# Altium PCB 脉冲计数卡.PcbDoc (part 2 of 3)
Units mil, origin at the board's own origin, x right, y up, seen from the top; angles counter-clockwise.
Board outline 5137.66 x 6771.53 mil, 4 copper layers (Top Layer, GND, VCC, Bottom Layer); 160 components, 225 nets, 1035 pads, 287 vias.
Unrouted connection lines stored in the file: 61.
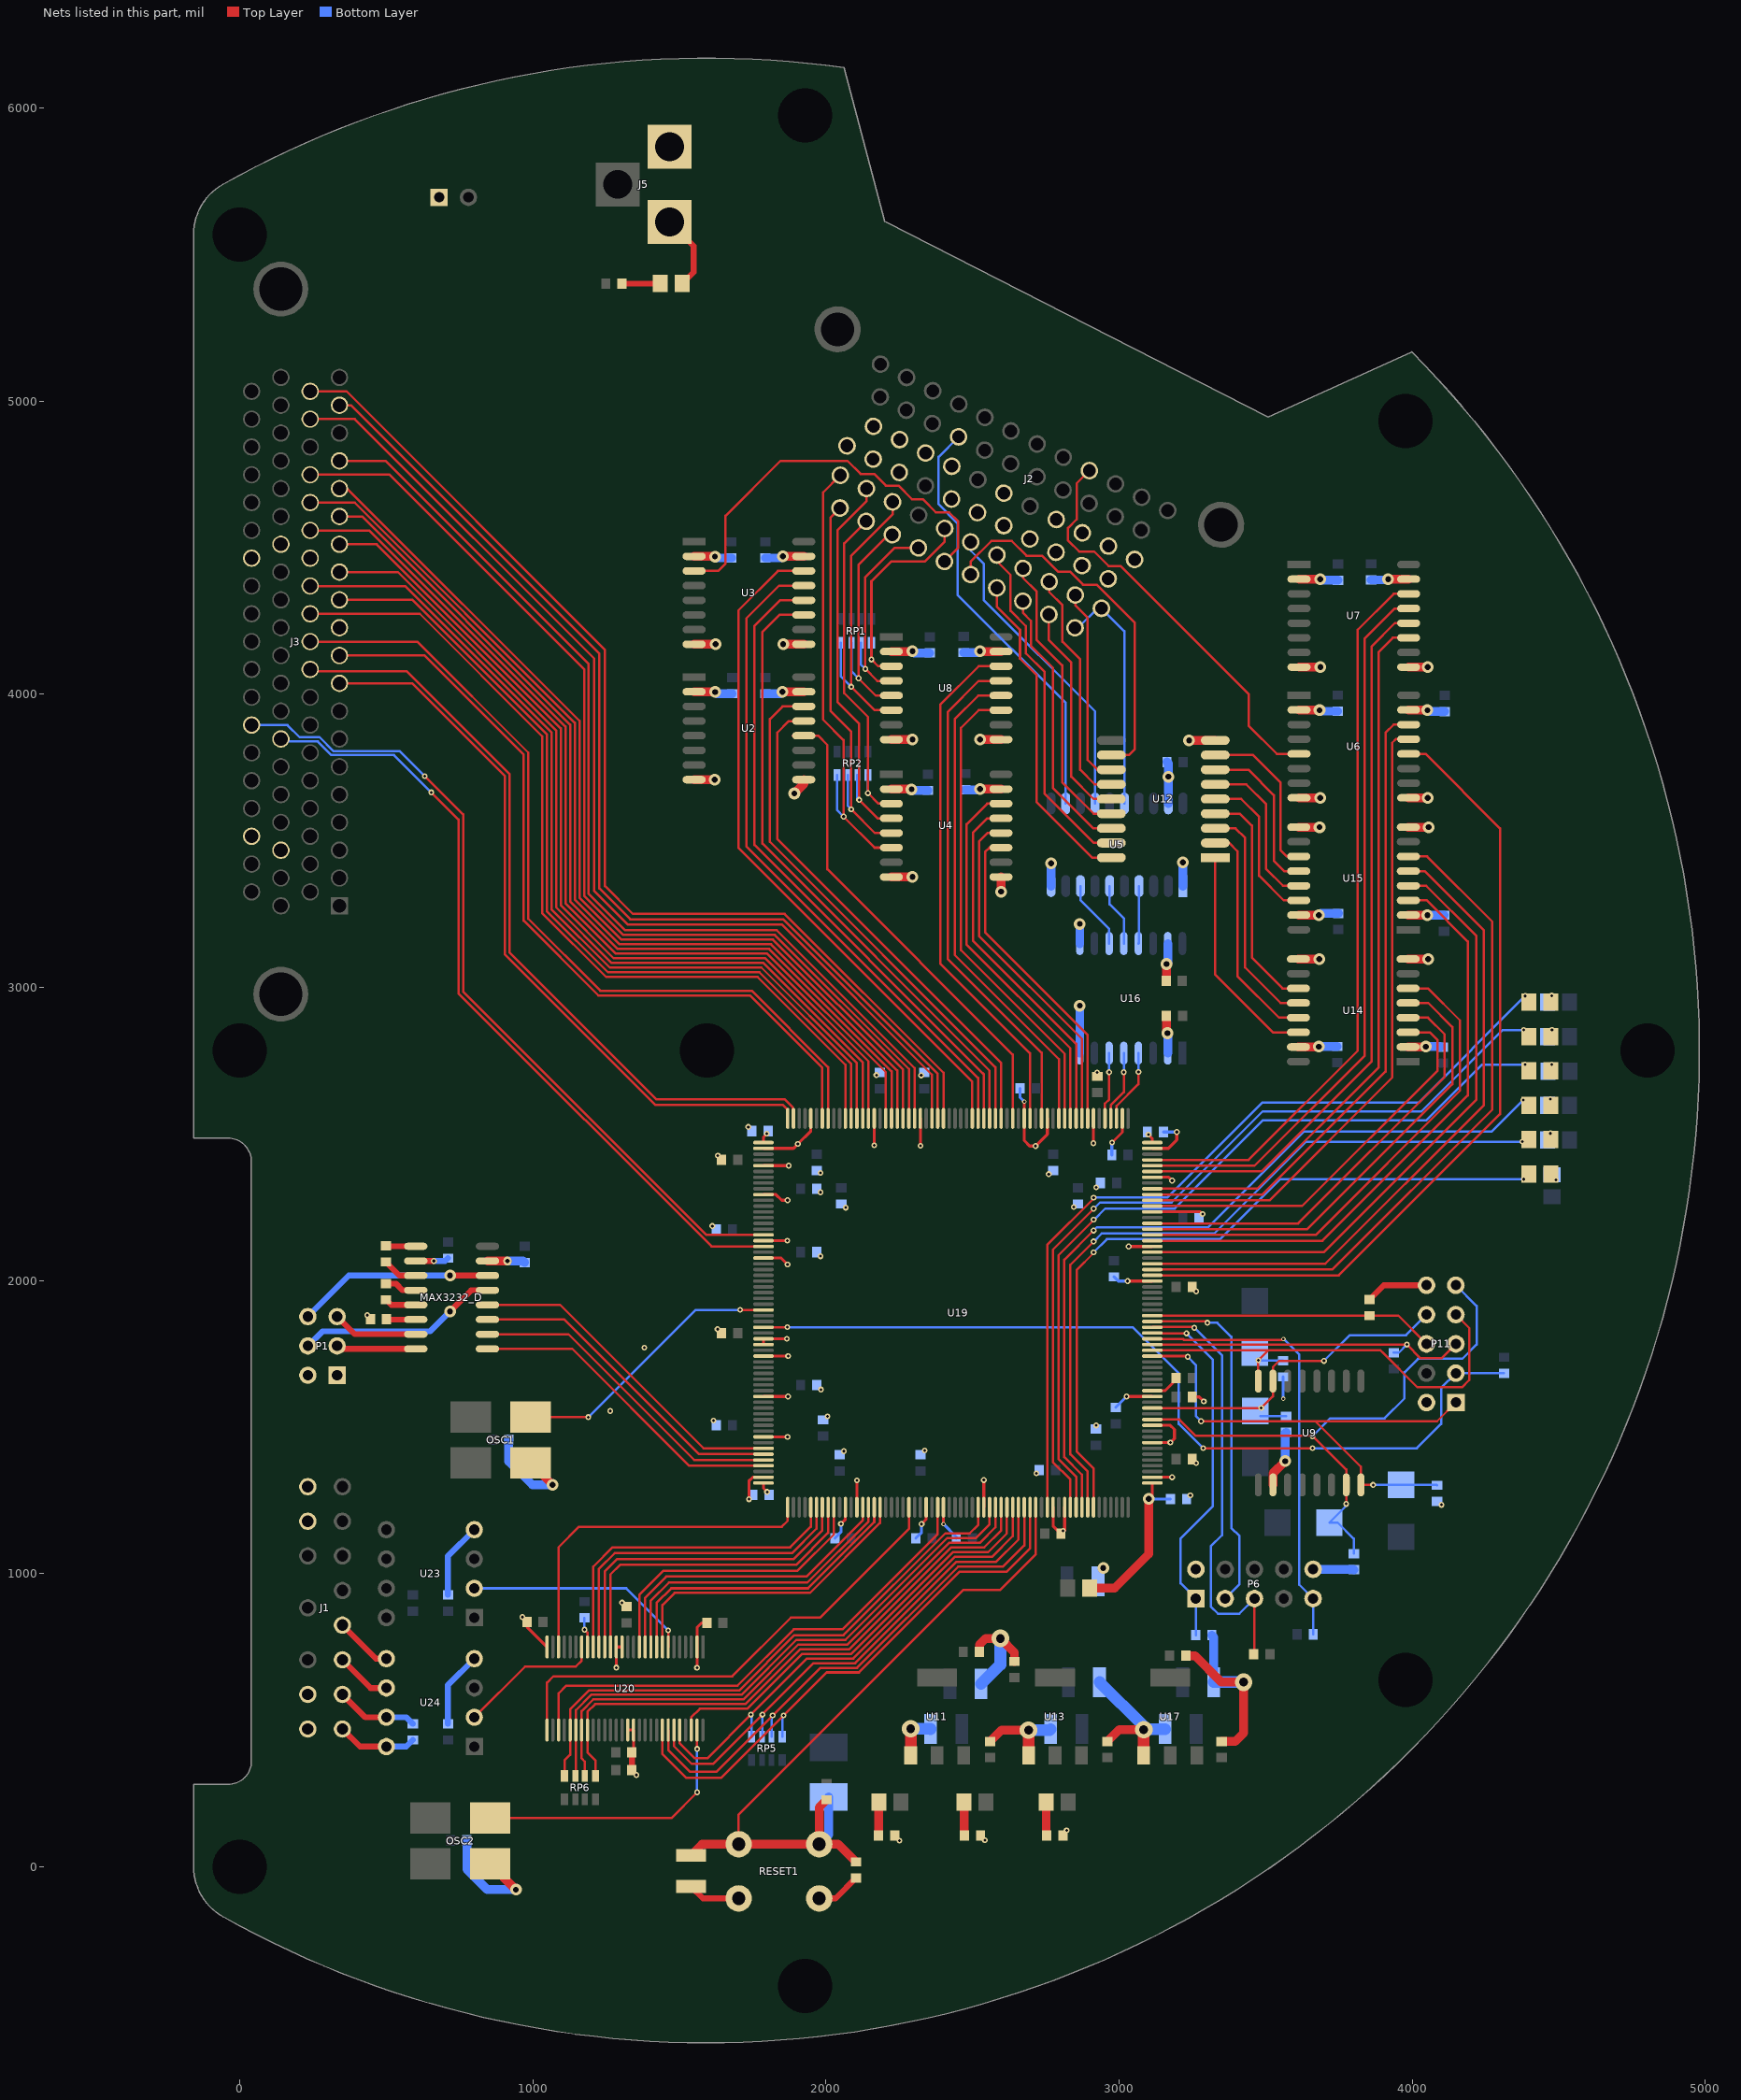
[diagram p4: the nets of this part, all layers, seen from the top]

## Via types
v1: diameter 20, hole 10, Top Layer to Bottom Layer, 184 vias
v2: diameter 40, hole 20, Top Layer to Bottom Layer, 82 vias
v3: diameter 15, hole 8, Top Layer to Bottom Layer, 11 vias
v4: diameter 60, hole 30, Top Layer to Bottom Layer, 8 vias
v5: diameter 30, hole 15, Top Layer to Bottom Layer, 2 vias

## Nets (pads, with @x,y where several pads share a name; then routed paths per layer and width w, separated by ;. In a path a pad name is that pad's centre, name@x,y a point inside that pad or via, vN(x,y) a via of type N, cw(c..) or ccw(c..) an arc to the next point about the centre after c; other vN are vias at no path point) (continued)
AA0: U12.7 U15.12 | length 559.5
  Top Layer w8: U12.7@3328,3743 3441,3743 3528,3656 3528,3432 3563,3397 U15.12@3612.98,3397
AA1: U12.5 U15.14 | length 546
  Top Layer w8: U12.5@3328,3643 3417,3643 3478,3582 3478,3381 3562,3297 U15.14@3612.98,3297
AA2: U12.6 U15.13 | length 557.8
  Top Layer w8: U12.6@3328,3693 3434,3693 3502,3625 3502,3404 3559,3347 U15.13@3612.98,3347
AA3: U12.3 U14.12 | length 789.8
  Top Layer w8: U12.3@3328,3543 3397,3543 3430,3510 3430,3068 3551,2947 U14.12@3611.98,2947
AA4: U12.4 U14.11 | length 794.5
  Top Layer w8: U12.4@3328,3593 3412,3593 3453,3552 3453,3102 3558,2997 U14.11@3611.98,2997
AA5: U12.1 U14.14 | length 764.6
  Top Layer w8: U12.1@3328,3443 3328,3044 3525,2847 U14.14@3611.98,2847
AA6: U12.2 U14.13 | length 780.4
  Top Layer w8: U12.2@3328,3493 3376,3493 3404,3465 3404,3039 3546,2897 U14.13@3611.98,2897
AA7: U12.8 U15.11 | length 563.6
  Top Layer w8: U12.8@3328,3793 3457,3793 3551,3699 3551,3468 3572,3447 U15.11@3612.98,3447
AB0: J2.48 U12.12 | length 627.2
  Top Layer w8: J2.48@2850.66,4338.99 2850.66,4304.34 2893,4262 2893,3776 U12.12@2926,3743
AB1: J2.49 U12.14 | length 753.3
  Top Layer w8: J2.49@2760.71,4272.59 2760.71,4185.29 2837,4109 2837,3719 2913,3643 U12.14@2973.67,3643
AB2: J2.50 U12.13 | length 812.4
  Top Layer w8: J2.50@2761.56,4384.39 2761.56,4349.44 2807,4304 2807,4180 2867,4120 2867,3743 2917,3693 U12.13@2973.67,3693
AB3: J2.51 U12.16 | length 936.2
  Top Layer w8: J2.51@2671.61,4317.99 2671.61,4278.39 2699,4251 2699,4166 2775,4090 2775,3680 2912,3543 U12.16@2973.67,3543
AB4: J2.52 U12.15 | length 997.1
  Top Layer w8: J2.52@2672.46,4429.79 2672.46,4397.54 2718,4352 2718,4187 2806,4099 2806,3700 2913,3593 U12.15@2973.67,3593
AB5: J2.53 U12.18 | length 1120.9
  Top Layer w8: J2.53@2582.51,4363.39 2582.51,4299.49 2662,4220 2662,4122 2719,4065 2719,3632 2908,3443 U12.18@2973.67,3443
AB6: J2.54 U12.17 | length 1178.8
  Top Layer w8: J2.54@2583.36,4475.19 2583.36,4453.64 2629.74,4407.26 2629.74,4285.26 2682,4233 2682,4140 2746,4076 2746,3661 2914,3493 U12.17@2973.67,3493
AB7: J2.55 U12.11 | length 1267.9
  Top Layer w8: J2.55@2493.41,4408.79 2493.41,4452.41 2564,4523 2634,4523 2684,4473 2737.31,4473 2791.31,4419 2832,4419 2877,4374 2923.71,4374 3054,4243.71 3054,3814 3033,3793 U12.11@2973.67,3793
ASDO: C29.2 D16.1 P11.9 U9.15 U19.12 | length 2067
  Top Layer w8: U19.12@3113.39,1525.83 3206.17,1525.83 3262,1470 3660,1470 3775,1355 U9.15@3775,1302.83 v1(3775,1238)
  Bottom Layer w8: v1(3660,1469) 3721,1530 3906,1530 3974,1598 3974,1687 4020,1733 4171,1733 4220,1782 4220,1913 P11.9@4149,1984 ; v1(3775,1238) 3775,1231.42 D16.1@3717.58,1174 3746,1174 3801,1119 C29.2@3801,1068.56
ASX+: U6.13 U19.50 | length 2195.2
  Top Layer w8: U19.50@3113.39,2273.86 3512.86,2273.86 3932,2693 3932,3835 3944,3847 U6.13@3988.02,3847
ASX-: U7.14 U19.57 | length 2515.8
  Top Layer w8: U19.57@3113.39,2411.65 3441.65,2411.65 3814,2784 3814,4220 3937,4343 U7.14@3988.02,4343
ASY+: U7.11 U19.52 | length 2483.3
  Top Layer w8: U19.52@3113.39,2313.23 3471.23,2313.23 3886,2728 3886,4145 3934,4193 U7.11@3988.02,4193
ASY-: U7.13 U19.56 | length 2495.6
  Top Layer w8: U19.56@3113.39,2391.97 3461.97,2391.97 3838,2768 3838,4191 3940,4293 U7.13@3988.02,4293
ASZ+: U6.14 U19.51 | length 2216
  Top Layer w8: U19.51@3113.39,2293.54 3489.54,2293.54 3909,2713 3909,3869 3937,3897 U6.14@3988.02,3897
ASZ-: U7.12 U19.55 | length 2479
  Top Layer w8: U19.55@3113.39,2372.28 3486.28,2372.28 3862,2748 3862,4164 3941,4243 U7.12@3988.02,4243
B2A: J1.1 R26.1 U24.8 | length 274.1
  Top Layer w20: J1.1@350,470 410,410 U24.8@500,410
  Bottom Layer w20: U24.8@500,410 567.56,410 R26.1@590,432.44
B2B: J1.2 R26.2 U24.7 | length 281.6
  Top Layer w20: J1.2@350,588.11 428.11,510 U24.7@500,510
  Bottom Layer w20: U24.7@500,510 567.56,510 R26.2@590,487.56
B2Y: J1.4 U24.5 | length 197.4
  Top Layer w20: J1.4@350,824.33 464.33,710 U24.5@500,710
B2Z: J1.3 U24.6 | length 189.9
  Top Layer w20: J1.3@350,706.22 446.22,610 U24.6@500,610
CEN: U19.202 U20.29 | length 1687.3
  Top Layer w8: U20.29@1048.13,466.64 1048.13,628.13 1070,650 1680,650 1880,850 1980,850 2282.68,1152.68 U19.202@2282.68,1226.61
CLK0: OSC1.3 U19.150 | length 946.3
  Top Layer w8: OSC1.3@992,1534 v1(1189,1534) ; v1(1707,1900) 1786.46,1900 U19.150@1786.61,1899.84
  Bottom Layer w8: v1(1189,1534) 1555,1900 v1(1707,1900)
CONF_DONE: P11.3 R5.1 U19.153 | length 2975.5
  Top Layer w8: U19.153@1786.83,1841 v1(1868,1841) ; v1(3287,1428) v1(3660,1428)
  Bottom Layer w8: v1@1869,1841 3046,1841 3204,1683 3204,1511 v1(3287,1428) ; v1(3660,1428) 4016,1428 4099,1511 4099,1634 P11.3@4149,1684 R5.1@4313.44,1684
D0: U19.185 U20.20 | length 1139
  Top Layer w8: U20.20@1205.61,750.1 1205.61,1023.61 1272,1090 1878,1090 1948.03,1160.03 U19.185@1948.03,1226.61
D1: U19.186 U20.19 | length 1138.4
  Top Layer w8: U20.19@1225.29,750.1 1225.29,1016.29 1279,1070 1884,1070 1967.72,1153.72 U19.186@1967.72,1226.61
D2: U19.187 U20.18 | length 1136.7
  Top Layer w8: U20.18@1244.98,750.1 1244.98,1006.98 1288,1050 1890,1050 1987.4,1147.4 U19.187@1987.4,1226.61
D3: U19.188 U20.17 | length 1135.9
  Top Layer w8: U20.17@1264.66,750.1 1264.66,997.31 1297.35,1030 1898,1030 2007.09,1139.09 U19.188@2007.09,1226.61
D4: U19.189 U20.12 | length 1019.1
  Top Layer w8: U20.12@1363.09,750.1 1363.09,927.09 1446,1010 1903,1010 2026.77,1133.77 U19.189@2026.77,1226.61
D5: U19.194 U20.11 | length 1064.5
  Top Layer w8: U20.11@1382.77,750.1 1382.77,917.77 1455,990 1933.86,990 2125.2,1181.34 U19.194@2125.2,1226.61
D6: U19.195 U20.10 | length 1060.7
  Top Layer w8: U20.10@1402.46,750.1 1402.46,908.46 1464,970 1936.3,970 2144.88,1178.58 U19.195@2144.88,1226.61
D7: U19.196 U20.9 | length 1057.5
  Top Layer w8: U20.9@1422.14,750.1 1422.14,900.14 1472,950 1938.75,950 2164.57,1175.81 U19.196@2164.57,1226.61
DATA0: C26.2 D13.1 P11.7 U9.8 U19.24 | length 1588.7
  Top Layer w8: U19.24@3113.39,1762.05 3891.95,1762.05 3901,1753 4018,1636 4170,1636 4195,1661 4195,1838 P11.7@4149,1884 ; U9.8@3475,1657.17 v1(3475,1728) 3509.02,1762.02
  Bottom Layer w8: v1(3475,1728) C26.2@3558.56,1728
DB8: J2.58 RP1.5 U8.3 | length 753.2
  Top Layer w8: U8.3@2223,4096 2178,4096 v1(2155,4119) 2155,4386 2222,4453 2337,4453 2405.16,4521.16 J2.58@2405.16,4565.99
  Bottom Layer w8: v1(2155,4119) RP1.5@2155,4176.71
DB8-A: U8.14 U19.78 | length 1799.7
  Top Layer w8: U8.14@2597.02,4096 2521,4096 2390,3965 2390,3082 2696.06,2775.94 U19.78@2696.06,2553.39
DB9: J2.59 RP1.6 U8.4 | length 737.4
  Top Layer w8: U8.4@2223,4046 2175,4046 v1(2134,4087) 2134,4400 2233.59,4499.59 J2.59@2315.21,4499.59
  Bottom Layer w8: RP1.6@2119,4176.71 2119,4102 v1(2134,4087)
DB9-A: U8.13 U19.76 | length 1745.3
  Top Layer w8: U8.13@2597.02,4046 2521,4046 2415,3940 2415,3098 2735.43,2777.57 U19.76@2735.43,2553.39
DB10: J2.61 RP1.7 U8.5 | length 812.9
  Top Layer w8: U8.5@2223,3996 2170,3996 v1(2111,4055) 2111,4442 2213.99,4544.99 J2.61@2226.11,4544.99
  Bottom Layer w8: RP1.7@2087,4176.71 2087,4079 v1(2111,4055)
DB10-A: U8.12 U19.73 | length 1700.4
  Top Layer w8: U8.12@2597.02,3996 2520,3996 2439,3915 2439,3111 2794.49,2755.51 U19.73@2794.49,2553.39
DB11: J2.62 RP1.8 U8.6 | length 1024.9
  Top Layer w8: U8.6@2223,3946 2166,3946 v1(2086,4026) 2086,4473 2226.95,4613.95 J2.62@2226.95,4656.79
  Bottom Layer w8: RP1.8@2050,4176.71 2050,4062 v1(2086,4026)
DB11-A: U8.11 U19.72 | length 1639.8
  Top Layer w8: U8.11@2597.02,3946 2521,3946 2461,3886 2461,3127 2814.17,2773.83 U19.72@2814.17,2553.39
DB12: J2.63 RP2.5 U4.3 | length 1148.6
  Top Layer w8: J2.63@2137.01,4590.39 2062,4515.38 2062,4004 2143,3923 v1(2143,3663) 2179,3627 U4.3@2223,3627
  Bottom Layer w8: v1(2143,3663) RP2.5@2143,3724.71
DB12-A: U4.14 U19.71 | length 1296.2
  Top Layer w8: U4.14@2597.02,3627 2550,3627 2480,3557 2480,3146 2833.86,2792.14 U19.71@2833.86,2553.39
DB13: J2.64 RP2.6 U4.4 | length 1357.1
  Top Layer w8: J2.64@2137.85,4702.19 2137.85,4658.85 2039,4560 2039,3974 2113,3900 v1(2113,3640) 2176,3577 U4.4@2223,3577
  Bottom Layer w8: RP2.6@2107,3724.71 2107,3646 v1(2113,3640)
DB13-A: U4.13 U19.70 | length 1237
  Top Layer w8: U4.13@2597.02,3577 2550,3577 2501,3528 2501,3160 2853.54,2807.46 U19.70@2853.54,2553.39
DB14: J2.65 RP2.7 U4.5 | length 1361.8
  Top Layer w8: J2.65@2047.9,4635.78 2016,4603.88 2016,3943 2086,3873 v1(2086,3608) 2167,3527 U4.5@2223,3527
  Bottom Layer w8: RP2.7@2075,3724.71 2075,3619 v1(2086,3608)
DB14-A: U4.12 U19.69 | length 1177.1
  Top Layer w8: U4.12@2597.02,3527 2551,3527 2522,3498 2522,3176 2873.23,2824.77 2873.23,2823.23 U19.69@2873.23,2553.39
DB15: J2.66 RP2.8 U4.6 | length 1575.6
  Top Layer w8: J2.66@2048.75,4747.58 1990,4688.83 1990,3914 2060,3844 v1(2060,3583) 2166,3477 U4.6@2223,3477
  Bottom Layer w8: RP2.8@2038,3724.71 2038,3605 v1(2060,3583)
DB15-A: U4.11 U19.68 | length 1113.7
  Top Layer w8: U4.11@2597.02,3477 2558,3477 2543,3462 2543,3188 2893,2838 ; U19.68@2892.91,2553.39 2892.91,2837.91
DCLK: C27.2 D14.1 P11.1 U9.16 U19.23 | length 1797.7
  Top Layer w8: U19.23@3113.39,1742.36 3231.64,1742.36 v1(3234,1740) ; v1(3280,1520) 3670,1520 ; v1(3866.83,1302.83) U9.16@3825,1302.83 3825,1365 3670,1520 ; P11.1@4149,1584 4085,1520 3670,1520
  Bottom Layer w8: v1(3234,1740) 3262,1712 3262,1538 v1(3280,1520) ; v1(3866.83,1302.83) D14.1@3961.75,1302.83 ; D14.1@3962,1302.58 4083.98,1302.58 C27.2@4085,1301.56
FA0: U15.5 U19.39 | length 2293.7
  Top Layer w8: U19.39@3113.39,2057.32 3703.32,2057.32 4245,2599 4245,3195 4043,3397 U15.5@3987,3397
FA1: U15.3 U19.43 | length 2068
  Top Layer w8: U19.43@3113.39,2136.06 3694.06,2136.06 4190,2632 4190,3157 4050,3297 U15.3@3987,3297
FA2: U15.4 U19.41 | length 2183
  Top Layer w8: U19.41@3113.39,2096.69 3698.69,2096.69 4219,2617 4219,3176 4048,3347 U15.4@3987,3347
FA3: U14.5 U19.45 | length 1608.4
  Top Layer w8: U19.45@3113.39,2175.43 3642.43,2175.43 4137,2670 4137,2865 4055,2947 U14.5@3986,2947
FA4: U14.6 U19.44 | length 1715.7
  Top Layer w8: U19.44@3113.39,2155.75 3670.75,2155.75 4163,2648 4163,2888 4054,2997 U14.6@3986,2997
FA5: U14.3 U19.49 | length 1380.5
  Top Layer w8: U19.49@3113.39,2254.17 3624.17,2254.17 4087,2717 4087,2820 4060,2847 U14.3@3986,2847
FA6: U14.4 U19.46 | length 1498.3
  Top Layer w8: U19.46@3113.39,2195.12 3611.12,2195.12 4111,2695 4111,2840 4054,2897 U14.4@3986,2897
FA7: U15.6 U19.38 | length 2405.5
  Top Layer w8: U19.38@3113.39,2037.64 3727.64,2037.64 4273,2583 4273,3225 4051,3447 U15.6@3987,3447
FOUT2: J3.38 U19.93 | length 3751.7
  Top Layer w8: J3.38@240,5033.94 364.06,5033.94 1246,4152 1246,3346 1341,3251 1859,3251 2400.79,2709.21 U19.93@2400.79,2553.39
FOUT3: J3.37 U19.94 | length 3606.9
  Top Layer w8: J3.37@340,4986.5 378.5,4986.5 1227,4138 1227,3338 1332,3233 1854,3233 2381.1,2705.9 U19.94@2381.1,2553.39
FOUT4: J3.36 U19.95 | length 3661.5
  Top Layer w8: J3.36@240,4939.06 391.94,4939.06 1209,4122 1209,3329 1323,3215 1849,3215 2361.42,2702.58 U19.95@2361.42,2553.39
FOUT7: J3.33 U19.98 | length 3451
  Top Layer w8: J3.33@340,4796.73 497.02,4796.73 1190.41,4103.34 1190.41,3319.78 1315.2,3194.98 1832.2,3194.98 2302.36,2724.83 U19.98@2302.36,2553.39
FOUT8: J3.32 U19.99 | length 3503.4
  Top Layer w8: J3.32@240,4749.29 510.71,4749.29 1174.54,4085.46 1174.54,3313.2 1308.63,3179.11 1825.63,3179.11 2282.68,2722.06 U19.99@2282.68,2553.39
FOUT9: J3.31 U19.100 | length 3263.5
  Top Layer w8: J3.31@340,4701.85 366.68,4701.85 1158.66,3909.87 1158.66,3306.63 1302.05,3163.24 1819.05,3163.24 2262.99,2719.3 U19.100@2262.99,2553.39
FOUT10: J3.30 U19.101 | length 3322.5
  Top Layer w8: J3.30@240,4654.41 391.67,4654.41 1142.79,3903.29 1142.79,3300.05 1295.48,3147.36 1812.48,3147.36 2243.31,2716.53 U19.101@2243.31,2553.39
FOUT11: J3.29 U19.102 | length 3181.6
  Top Layer w8: J3.29@340,4606.97 416.66,4606.97 1126.91,3896.72 1126.91,3293.48 1288.9,3131.49 1805.9,3131.49 2223.62,2713.77 U19.102@2223.62,2553.39
FOUT12: J3.28 U19.103 | length 3240.6
  Top Layer w8: J3.28@240,4559.53 441.65,4559.53 1111.04,3890.14 1111.04,3286.9 1282.33,3115.61 1799.33,3115.61 2203.94,2711 U19.103@2203.94,2553.39
FOUT15: J3.25 U19.107 | length 3022.7
  Top Layer w8: J3.25@340,4417.2 539.08,4417.2 1079.29,3876.99 1079.29,3273.75 1269.18,3083.87 1786.18,3083.87 2125.2,2744.85 U19.107@2125.2,2553.39
FOUT16: J3.24 U19.108 | length 3081.8
  Top Layer w8: J3.24@240,4369.76 564.07,4369.76 1063.42,3870.42 1063.42,3267.18 1262.6,3067.99 1779.6,3067.99 2105.51,2742.08 U19.108@2105.51,2553.39
FOUT17: J3.23 U19.109 | length 2940.8
  Top Layer w8: J3.23@340,4322.32 589.06,4322.32 1047.54,3863.84 1047.54,3260.6 1256.03,3052.12 1773.03,3052.12 2085.83,2739.32 U19.109@2085.83,2553.39
FOUT18: J3.22 U19.110 | length 2999.9
  Top Layer w8: J3.22@240,4274.88 614.05,4274.88 1031.67,3857.27 1031.67,3254.03 1249.45,3036.24 1766.45,3036.24 2066.14,2736.55 U19.110@2066.14,2553.39
FOUT20: J3.20 U19.113 | length 2875.5
  Top Layer w8: J3.20@240,4180 605.38,4180 984.05,3801.34 984.05,3234.3 1229.73,2988.62 1746.73,2988.62 2007.09,2728.26 U19.113@2007.09,2553.39
FOUT21: J3.19 U19.114 | length 2734.5
  Top Layer w8: J3.19@340,4132.56 630.38,4132.56 968.17,3794.76 968.17,3227.73 1223.15,2972.75 1740.15,2972.75 1987.4,2725.5 U19.114@1987.4,2553.39
FOUT22: J3.18 U19.119 | length 2657.4
  Top Layer w8: J3.18@240,4085.12 246.04,4079.08 568.37,4079.08 920.55,3726.9 920.55,3118.9 1420.45,2619 1858.35,2619 1887.07,2590.28 U19.119@1887.07,2555.29
FOUT23: J3.17 U19.120 | length 2517.4
  Top Layer w8: J3.17@340,4037.68 587.32,4037.68 904.68,3720.32 904.68,3112.32 1417,2600 1852,2600 1869.29,2582.71 U19.120@1869.29,2553.39
FUSE: C61.2 C62.2 C63.2 C64.2 F1.1 U19.1 U19.60 U19.121 U19.180 | length 673.8
  Top Layer w10: U19.180@1786.61,1309.29 1786.61,1291.39 v1(1799,1279) ; U19.121@1786.61,2470.71 1786.61,2489.61 v1(1798,2501) ; v1(3100,2498) 3113.39,2484.61 U19.60@3113.39,2470.71 ; v2(3101,1255) 3113.39,1267.39 U19.1@3113.39,1309.29
  Top Layer w30: F1.1@2899.4,951 2985,951 3101,1067 v2(3101,1255)
  Bottom Layer w10: v2(3101,1255) C61.2@3174.44,1255
GD-EN: J2.7 U6.5 | length 1421.4
  Top Layer w8: J2.7@2898.6,4763.49 2855,4719.89 2855,4597 2826,4568 2826,4525 2864,4487 2915,4487 2964,4438 3005,4438 3442,4001 3442,3893 3538,3797 U6.5@3614,3797
GD-EN-A: U6.12 U19.37 | length 2806.6
  Top Layer w8: U19.37@3113.39,2017.95 3749.95,2017.95 4300,2568 4300,3543 4046,3797 U6.12@3988.02,3797
GND1: C1.1 C3.1 C5.1 C7.1 C9.1 C11.1 C13.1 C14.1 C16.1 C18.1 J2.24 J2.25 J2.26 J2.27 J2.28 J2.29 J2.30 J2.31 J2.33 J2.34 J2.35 J2.37 J2.38 J2.40 J2.41 J2.42 J2.43 J2.44 J2.45 J5.1 J5.2 LED4.2 P3.1 U2.2 U2.8 U3.2 U3.8 U4.2 U4.8 U5.1 U5.10 U5.19 U6.2 U6.8 U7.2 U7.8 U8.2 U8.8 U12.9 U14.9 U14.15 U15.9 U15.15 U16.9 U16.15 | length 2482.1
  Top Layer w20: J5.1@1466,5612 1548,5530 1548,5440.6 LED4.2@1509.4,5402
  Top Layer w30: U2.8@1550,3709 v2(1620,3709) ; U2.2@1550,4009 1621,4009 v2(1622,4008) ; U3.8@1550,4171 v2(1623,4171) ; U3.2@1550,4471 1620,4471 v2(1621,4470) ; U4.8@2223,3377 v2(2295,3377) ; U4.2@2223,3677 2291,3677 v2(2292,3676) ; U8.8@2223,3846 v2(2295,3846) ; U8.2@2223,4146 2294,4146 v2(2295,4147) ; C3.1@3160.44,3023 3162,3024.56 v2(3162,3080) ; v2(3239,3843) U12.9@3328,3843 ; U14.15@3611.98,2797 3681,2797 v2(3682,2798) ; U14.9@3611.98,3097 v2(3683,3097) ; U15.15@3612.98,3247 v2(3682,3247) ; U15.9@3612.98,3547 v2(3684,3547) ; U6.8@3614,3647 v2(3686,3647) ; U6.2@3614,3947 3683,3947 v2(3684,3946) ; U7.8@3614,4093 v2(3687,4093) ; U7.2@3614,4393 v2(3686,4393)
  Bottom Layer w30: v2(1621,4470) 1625.56,4465.44 C1.1@1677,4465.44 ; v2(1622,4008) 1627.56,4002.44 C5.1@1680,4002.44 ; v2(2292,3676) 2295.56,3672.44 C9.1@2348,3672.44 ; v2(2295,4147) 2300.56,4141.44 C7.1@2354,4141.44 ; U5.10@2768,3346.06 v2(2768,3424) ; U16.9@2866,3150.02 v2(2866,3217) ; v2(3162,3080) 3166,3084 U16.15@3166,3150.02 ; C13.1@3163.44,3769 3168,3764.44 U5.19@3168,3627.94 ; U5.1@3218,3346.06 v2(3218,3427) ; v2(3682,2798) 3682.56,2798.56 C18.1@3744,2798.56 ; v2(3682,3247) 3687.56,3252.56 C16.1@3748,3252.56 ; v2(3684,3946) 3687.56,3942.44 C14.1@3746,3942.44 ; v2(3686,4393) 3689.56,4389.44 C11.1@3747,4389.44
  other v2: 3168,3719
GND2: C2.1 C4.1 C6.1 C8.1 C10.1 C12.1 C15.1 C17.1 C19.1 C22.1 C25.1 C26.1 C27.1 C28.1 C29.1 C30.1 C31.1 C32.1 C33.1 C34.1 C35.1 C36.1 C37.1 C38.1 C39.1 C40.1 C41.1 C42.1 C43.1 C44.1 C45.1 C46.2 C47.2 C48.1 C49.1 C50.1 C51.1 C52.1 C53.1 C54.2 C55.2 C56.1 C57.2 C58.1 C59.1 C60.1 C61.1 C62.1 C63.1 C64.1 C65.1 C66.1 C67.1 C68.1 C69.1 C70.1 C71.1 C72.1 C73.1 C74.1 C75.1 C76.1 C77.1 C78.1 C79.1 C80.1 C81.1 CP1.2 CP2.2 CP3.2 CP4.2 CP5.2 CP6.2 CP7.2 CP8.2 J1.9 J1.10 J1.14 J1.15 J3.21 J3.26 J3.52 J3.53 J3.73 J3.74 MAX3232_D.15 OSC1.2 OSC2.2 P1.1 P1.2 P6.2 P6.10 P11.2 P11.10 R6.2 R7.2 R8.1 R9.1 R11.2 RESET1.1 U2.9 U2.15 U3.9 U3.15 U4.9 U4.15 U6.9 U6.15 U7.9 U7.15 U8.9 U8.15 U9.10 U11.1 U13.1 U14.2 U14.8 U15.2 U15.8 U16.2 U16.8 U17.1 U19.2 U19.8 U19.11 U19.16 U19.36 U19.42 U19.48 U19.54 U19.59 U19.62 U19.67 U19.75 U19.79 U19.97 U19.105 U19.116 U19.122 U19.125 U19.130 U19.138 U19.141 U19.155 U19.156 U19.158 U19.165 U19.172 U19.179 U19.191 U19.193 U19.205 U19.208 U19.215 U19.227 U19.229 U20.2 U20.15 U20.16 U20.28 U20.43 U20.44 U23.4 U24.4 | length 10518
  Top Layer w10: C50.1@979.44,835 979.44,818.79 U20.28@1048.13,750.1 ; v1(1284.35,679.35) U20.16@1284.35,750.1 U20.15@1304.03,750.1 ; U20.43@1323.72,466.64 U20.44@1343.4,466.64 C53.1@1343.4,395.84 ; v1(1559.94,679.06) U20.2@1559.94,750.1 1559.94,815.94 1576,832 C56.1@1593.44,832 ; v1@1738.31,1255.31 v1(1737,1254) 1737,1316 1749.98,1328.98 U19.179@1786.61,1328.98 ; U19.172@1786.61,1466.77 v1(1868.77,1466.77) ; U19.165@1786.61,1604.57 v1(1870.57,1604.57) ; U19.158@1786.61,1742.36 v1(1870.64,1742.36) ; U19.156@1786.61,1781.73 U19.155@1786.61,1801.42 v1(1866.42,1801.42) ; U19.141@1786.61,2077.01 1846.99,2077.01 v1(1869,2055) ; U19.138@1786.61,2136.06 v1(1867.94,2136.06) ; U19.130@1786.61,2293.54 1829.46,2293.54 1849,2274 v1(1869,2274) ; U19.125@1786.61,2391.97 v1(1872.97,2391.97) ; U19.122@1786.61,2451.02 1889.02,2451.02 v1(1904,2466) 1948.03,2510.03 U19.116@1948.03,2553.39 ; v1(2051,1170) 2066.14,1185.14 U19.191@2066.14,1226.61 ; U19.193@2105.51,1226.61 v1(2105.51,1318.51) ; v1(2164.57,2461.43) U19.105@2164.57,2553.39 ; v1(2322.05,2460.05) U19.97@2322.05,2553.39 ; v1(2326,1169) 2341.73,1184.73 U19.205@2341.73,1226.61 ; v3(2400.79,1169.21) U19.208@2400.79,1226.61 ; U19.215@2538.58,1226.61 v1(2538.58,1319.42) ; v3(2676.38,2610.62) U19.79@2676.38,2553.39 2676.38,2477.62 2695,2459 v1(2715,2459) 2755.12,2499.12 U19.75@2755.12,2553.39 ; U19.227@2774.8,1226.61 2774.8,1162.76 C69.1@2801.56,1136 2814.17,1148.61 U19.229@2814.17,1226.61 ; v1(2912.6,2468.4) U19.67@2912.6,2553.39 ; v1(2976,2471) 3011.02,2506.02 U19.62@3011.02,2553.39 ; v1(3025.43,1604.57) U19.16@3113.39,1604.57 ; v1(3029.27,1998.27) U19.36@3113.39,1998.27 ; v1(3032.62,2116.38) U19.42@3113.39,2116.38 ; U19.2@3113.39,1328.98 v1(3180.98,1328.98) ; U19.8@3113.39,1447.09 v1(3174.91,1447.09) 3189,1461.17 3189,1492 3174.86,1506.14 U19.11@3113.39,1506.14 ; U19.48@3113.39,2234.49 3114.07,2235.18 3276.82,2235.18 v1(3285,2227) ; U19.54@3113.39,2352.6 3169.4,2352.6 v1(3181,2341) ; U19.59@3113.39,2451.02 3168.02,2451.02 3197,2480 v1(3197,2507) ; C79.1@3249.56,1603 3274,1603 v1(3289,1588)
  Top Layer w20: C51.1@1337.56,330 C53.1@1337.56,390 ; CP8.2@1539,-67.15 1579.85,-108 RESET1.1@1702,-108 ; RESET1.1@1977,-108 2032.56,-108 C81.1@2102,-38.56 ; R8.1@3855,1935.56 3903.44,1984 P11.10@4049,1984
  Top Layer w30: MAX3232_D.15@845,2067 v5(913,2067) ; OSC2.2@854,10 v2(942,-78) ; OSC1.2@992,1378 v2(1067,1303) ; v2(1851,4009) U2.15@1924.02,4009 ; v2(1853,4471) U3.15@1924.02,4471 ; v2(1854,4171) U3.9@1924.02,4171 ; v2(1892,3662) 1924.02,3694.02 U2.9@1924.02,3709 ; C31.1@2523.56,733 2523.56,757.56 2545,779 v4(2595,779) 2643,731 C33.1@2643,700.56 ; v2(2525,4147) 2526,4146 U8.15@2597.02,4146 ; v2(2526,3677) U4.15@2597.02,3677 ; v2(2526,3846) U8.9@2597.02,3846 ; C30.1@2560,427.56 2598.44,466 v4(2691,466) ; v2(2597.02,3326.98) U4.9@2597.02,3377 ; C32.1@2960,427.56 3000.44,468 v4(3084,468) ; C19.1@3161.44,2903 3161.44,2847.56 v2(3165,2844) ; C49.1@3227.56,720 3259,720 3349,630 v4(3425,630) 3425,456 3396.56,427.56 C48.1@3350,427.56 ; U9.10@3525,1302.83 3525,1342 v2(3567,1384) ; v2(3918,4393) U7.15@3988.02,4393 ; U14.2@3986,2797 4048,2797 v2(4047,2798) ; U14.8@3986,3097 v2(4055,3097) ; U15.2@3987,3247 v2(4052,3247) ; U15.8@3987,3547 v2(4056,3547) ; U6.9@3988.02,3647 v2(4053,3647) ; U6.15@3988.02,3947 4051,3947 v2(4052,3946) ; U7.9@3988.02,4093 v2(4053,4093)
  Top Layer w40: U11.1@2289,380 v4(2289,471) ; U13.1@2691,380 v4(2691,466) ; U17.1@3084,380 v4(3084,468)
  Bottom Layer w10: C72.1@2030.44,1121 2051,1141.56 v1(2051,1170) ; C71.1@2306.44,1121 2326,1140.56 v1(2326,1169) ; v3(2400.79,1169.21) 2444.44,1125.56 C70.1@2444.44,1121 ; C73.1@2661.44,2656.41 2661.44,2625.56 v3(2676.38,2610.62) ; C43.1@2975.44,2428.59 v1@2975.44,2470.44 ; C45.1@2983,2012.44 2997.17,1998.27 v1(3029.27,1998.27) ; C37.1@2989,1566.56 2989,1568.13 v1(3025.43,1604.57) ; C62.1@3151.56,2507 v1(3197,2507) ; v3(3560,1597) C26.1@3560,1671.44
  Bottom Layer w20: C54.2@710,487.56 710,620 U24.4@800,710 ; C55.2@710,927.56 710,1060 U23.4@800,1150 ; v5(913,2067) v5@918.56,2061.44
  Bottom Layer w30: C46.2@774.56,90 774.56,-8.56 844,-78 v2(942,-78) ; v5(913,2067) 966.44,2067 C22.1@972,2061.44 ; C47.2@917.56,1457 917.56,1383.44 998,1303 v2(1067,1303) ; C4.1@1793,4002.44 1844.44,4002.44 v2(1851,4009) ; C2.1@1793,4465.44 1847.44,4465.44 v2(1853,4471) ; C6.1@2470,4142.44 2520.44,4142.44 v2(2525,4147) ; C8.1@2475,3674.44 2523.44,3674.44 v2(2526,3677) ; U16.8@2866,2776 v2(2866,2938) ; v2(3165,2844) 3166,2843 U16.2@3166,2776 ; R9.1@3316.56,790 3323.15,783.41 CP6.2@3323.15,630 ; v2(3567,1384) 3567,1479.44 C28.1@3570,1482.44 ; P6.10@3662,1015 3799.44,1015 C29.1@3801,1013.44 ; C10.1@3860,4390.44 3915.44,4390.44 v2(3918,4393) ; v2(4047,2798) 4095.56,2798 C17.1@4097,2796.56 ; v2(4052,3247) 4108.56,3247 C15.1@4109,3246.56 ; v2(4052,3946) 4056.56,3941.44 C12.1@4111,3941.44
  Bottom Layer w40: v4(2289,471) 2355.85,471 CP1.2@2356.85,470 ; CP2.2@2529.15,624 2595,689.85 v4(2595,779) ; v4(2691,466) 2762.85,466 CP3.2@2766.85,470 ; CP4.2@2933.15,630 3084,479.15 v4(3084,468) 3086,470 CP5.2@3156.85,470 ; CP6.2@3323.15,630 v4(3425,630)
  other v1: 2251,89 2542,91 2821,124 1353,313 964,852 1304,901 2809,1146 4100,1235 3243,1267 2718,1342 3263,1377 2061,1418 2337,1420 2922,1506 1616,1522 2005,1537 1264,1555 1983,1628 1380,1771 1630,1834 435,1882 3263,1963 1981,2083 1612,2186 2067,2249 2845,2251 1981,2301 2922,2318 2760,2363 1981,2367 1631,2426 1735,2524 2325,2700 2172,2701 2925,2710
  other v2: 2946,1019
I/M: R1.2 U20.21 | length 103.4
  Top Layer w8: v1(1175.92,809) 1185.92,799 U20.21@1185.92,750.1
  Bottom Layer w8: v1(1175.92,809) R1.2@1175.92,849.36
IACKN: U19.181 U20.26 | length 1205.4
  Top Layer w8: U20.26@1087.5,750.1 1087.5,1090 1157.5,1160 1849,1160 1869.29,1180.29 U19.181@1869.29,1226.61
IO0A: RP5.5 U19.220 U20.52 | length 1688.5
  Top Layer w8: U20.52@1500.88,466.64 1500.88,420.88 1551.76,370 1595,370 v1(1744,519) 1935.63,710.63 2092.88,710.63 2439.25,1057 2566.37,1057 2637.01,1127.64 U19.220@2637.01,1226.61
  Bottom Layer w8: RP5.5@1746,444.29 v1@1746,517
IO1A: RP5.6 U19.221 U20.51 | length 1756.3
  Top Layer w8: U20.51@1481.2,466.64 1481.2,411.8 1542,351 1614,351 1957.76,694.76 2099.45,694.76 2444.07,1039.38 2579.38,1039.38 2656.69,1116.69 U19.221@2656.69,1226.61
  Bottom Layer w8: RP5.6@1782,444.29 v1@1782,518
  other v1: 1783,519
IO2A: RP5.7 U19.222 U20.50 | length 1831.7
  Top Layer w8: U20.50@1461.51,466.64 1461.51,398.49 1536,324 1626,324 v1(1818,516) 1980.88,678.88 2106.03,678.88 2450.65,1023.5 2603.5,1023.5 2676.38,1096.38 U19.222@2676.38,1226.61
  Bottom Layer w8: RP5.7@1814,444.29 v1@1814,512
IO3A: RP5.8 U19.223 U20.49 | length 1902.9
  Top Layer w8: U20.49@1441.83,466.64 1441.83,384.17 1523,303 1642,303 v1(1855,516) 2002.01,663.01 2112.6,663.01 2456.59,1007 2616.99,1007 2696.06,1086.07 U19.223@2696.06,1226.61
  Bottom Layer w8: RP5.8@1851,444.29 v1@1851,512
IO4B: RP6.5 U19.218 U20.36 | length 1976.6
  Top Layer w8: RP6.5@1213,310.29 1213,363 1185.92,390.08 U20.36@1185.92,466.64 1185.92,528.57 1212.1,554.76 1724.55,554.76 1912.17,742.38 2079.73,742.38 2427.35,1090 2540,1090 2597.64,1147.64 U19.218@2597.64,1226.61
IO5B: RP6.6 U19.217 U20.35 | length 1965.4
  Top Layer w8: RP6.6@1177,310.29 1177,359 1166.24,369.76 U20.35@1166.24,466.64 1166.24,531.34 1205.53,570.63 1717.98,570.63 1905.6,758.25 2073.15,758.25 2420.77,1105.87 2525.87,1105.87 2577.95,1157.95 U19.217@2577.95,1226.61
IO6B: RP6.7 U19.216 U20.34 | length 1955
  Top Layer w8: RP6.7@1146.55,311.84 U20.34@1146.55,466.64 1146.55,534.1 1198.95,586.5 1711.4,586.5 1899.02,774.13 2066.58,774.13 2414.2,1121.75 2511.75,1121.75 2558.27,1168.27 U19.216@2558.27,1226.61
IO7B: RP6.8 U19.214 U20.33 | length 1947.7
  Top Layer w8: RP6.8@1108,310.29 1108,363 1126.87,381.87 U20.33@1126.87,466.64 1126.87,536.87 1192.38,602.38 1704.83,602.38 1892.45,790 2060,790 2407.62,1137.62 2490.62,1137.62 2518.9,1165.9 U19.214@2518.9,1226.61
IRQN: U19.219 U20.54 | length 1469.4
  Top Layer w8: U20.54@1540.25,466.64 1540.25,509.75 1569.39,538.88 1731.13,538.88 1918.75,726.5 2086.3,726.5 2432.67,1072.87 2552.87,1072.87 2617.32,1137.32 U19.219@2617.32,1226.61
JTAG_TCK: P6.1 R9.2 U19.27 | length 1249.3
  Top Layer w8: U19.27@3114.49,1820 v1(3230,1820)
  Bottom Layer w8: v1(3230,1820) 3320,1730 3320,1230 3210,1120 3210,967 P6.1@3262,915 R9.2@3262,790.56
JTAG_TDI: P6.9 R2.1 U19.26 | length 1499.4
  Top Layer w8: U19.26@3113.39,1801.42 3113.8,1801 3218.07,1801 3220.94,1798.13 3558.13,1798.13 v3(3561,1801)
  Bottom Layer w8: v3(3561,1801) 3615,1747 3615,962 P6.9@3662,915 R2.1@3662,793.56
JTAG_TDO: P6.3 U19.29 | length 1213
  Top Layer w8: U19.29@3113.79,1860.87 v1@3300,1860.87
  Bottom Layer w8: v1(3301,1856) 3335,1856 3383,1808 3383,1156 3411,1128 3411,964 P6.3@3362,915
JTAG_TMS: P6.5 R3.1 U19.28 | length 1521.3
  Top Layer w8: U19.28@3114.47,1841.87 3254.13,1841.87 v1(3257,1839) ; R3.1@3459.44,725 3462,727.56 P6.5@3462,915
  Bottom Layer w8: v1(3257,1839) 3351,1745 3351,1131 3313,1093 3313,888 3338,863 3410,863 P6.5@3462,915
LAX+: U2.14 U19.84 | length 1814
  Top Layer w8: U2.14@1924.02,3959 1852,3959 1809,3916 1809,3497 2577.95,2728.05 U19.84@2577.95,2553.39
LAX-: U3.12 U19.86 | length 2214
  Top Layer w8: U3.12@1924.02,4321 1843,4321 1756,4234 1756,3486 2538.03,2703.97 ; 2534.77,2707.78 2538.58,2703.97 U19.86@2538.58,2553.39
LAY+: U3.11 U19.85 | length 2145.8
  Top Layer w8: U3.11@1924.02,4271 1841,4271 1783,4213 1783,3491 2558.27,2715.73 U19.85@2558.27,2553.39
LAY-: U3.13 U19.87 | length 2275.6
  Top Layer w8: U3.13@1924.02,4371 1840,4371 1728,4259 1728,3482 2518.9,2691.1 U19.87@2518.9,2553.39
LAZ+: U2.12 U19.81 | length 1667.7
  Top Layer w8: U2.12@1886,3859 U2.12@1924.02,3859 1973,3859 2005,3827 2005,3403 2637.01,2770.99 U19.81@2637.01,2553.39
LAZ-: U2.13 U19.83 | length 1739.1
  Top Layer w8: U2.13@1924.02,3909 1873,3909 1834,3870 1834,3506 2597.64,2742.36 U19.83@2597.64,2553.39
LED1: LED6.2 U19.226 | length 2879.8
  Top Layer w8: U19.226@2755.12,1226.61 2755.12,2122.12 2913,2280 v1(2913,2283)
  Bottom Layer w8: v1(2913,2283) 3164,2283 3489,2608 4023,2608 v1(4386,2971)
LED2: LED7.2 U19.230 | length 2821.8
  Top Layer w8: U19.230@2833.86,1226.61 2833.86,1321.14 2774,1381 2774,2105 2913,2244 v1(2913,2245.6)
  Bottom Layer w8: v1(2913,2245.6) 2914.6,2245.6 2935,2266 3179,2266 3490,2577 4031,2577 4309,2855 v1(4381,2855)
LED3: LED8.2 U19.231 | length 2745.2
  Top Layer w8: U19.231@2853.54,1226.61 2853.54,1330.46 2793,1391 2793,2086 v1@2913,2206
  Bottom Layer w8: v1(2913,2208.2) 2915.2,2208.2 2953,2246 3190,2246 3491,2547 4049,2547 4239,2737 v1(4385,2737)
LED4: LED9.2 U19.232 | length 2661
  Top Layer w8: U19.232@2873.23,1226.61 2873.23,1337.77 2813,1398 2813,2070.8 v1(2913,2170.8)
  Bottom Layer w8: v1(2913,2170.8) 2924.2,2182 3304,2182 3631,2509 4272,2509 v1(4379,2616)
LED5: LED10.2 U19.233 | length 2568
  Top Layer w8: U19.233@2892.91,1226.61 2892.91,1348.09 2834,1407 2834,2054 2913,2133 v1(2913,2133.4)
  Bottom Layer w8: v1(2913,2133.4) 2913.4,2133.4 2941,2161 3325,2161 3638,2474 v1(4376,2474)
LED6: LED11.2 U19.234 | length 2488.8
  Top Layer w8: U19.234@2912.6,1226.61 2912.6,1359.4 2855,1417 2855,2036 2913,2094 v1(2913,2096)
  Bottom Layer w8: v1(2913,2096) 2958,2141 3345,2141 3550,2346 v1(4381,2346)
NCE: P11.6 R8.2 U19.30 | length 975.4
  Top Layer w8: U19.30@3113.39,1880.16 3952.84,1880.16 P11.6@4049,1784
NCONFIG: P11.5 R4.1 U19.25 | length 1132.3
  Top Layer w8: U19.25@3113.39,1781.73 3113.49,1781.63 3569.02,1781.63 3569.13,1781.73 v1(3982.27,1781.73) 4029,1735 4100,1735 P11.5@4149,1784
  Bottom Layer w8: R4.1@3937,1753.56 3954.09,1753.56 v1(3982.27,1781.73)
NCSO: C28.2 D15.1 P11.8 U9.7 U19.14 | length 1213.2
  Top Layer w8: U19.14@3113.39,1565.2 v1(3485.2,1565.2) 3525,1605 U9.7@3525,1657.17 3525,1705 3546,1726 v1(3699,1726)
  Bottom Layer w8: D15.1@3483.02,1537.56 C28.2@3570,1537.56 ; v1(3699,1726) 3787,1814 3979,1814 P11.8@4049,1884
NetC20_1: C20.1 MAX3232_D.3 | length 121.2
  Top Layer w20: C20.1@498,2063.44 544.44,2017 MAX3232_D.3@600,2017
NetC20_2: C20.2 MAX3232_D.1 | length 100.4
  Top Layer w20: C20.2@499.56,2117 MAX3232_D.1@600,2117
NetC21_1: C21.1 MAX3232_D.2 | length 124.6
  Top Layer w8: MAX3232_D.2@592.44,2059.44 MAX3232_D.2@600,2067
  Top Layer w20: MAX3232_D.2@600,2067 v1(662,2067)
  Bottom Layer w20: v1(662,2067) 700.56,2067 C21.1@710,2076.44
NetC24_1: C24.1 MAX3232_D.5 | length 108.2
  Top Layer w20: C24.1@499,1934.44 516.44,1917 MAX3232_D.5@600,1917
NetC24_2: C24.2 MAX3232_D.4 | length 121
  Top Layer w8: MAX3232_D.4@592.44,1974.56 MAX3232_D.4@600,1967
  Top Layer w20: C24.2@499,1989.56 532.46,1989.56 555.02,1967 MAX3232_D.4@600,1967
NetC25_2: C25.2 MAX3232_D.6 | length 98.4
  Top Layer w20: C25.2@501.56,1867 MAX3232_D.6@600,1867
NetLED1_2: 5V1.2 R7.1 | length 111.8
  Top Layer w30: R7.1@2180.2,108.16 5V1.2@2180.2,220
NetLED2_2: 3.3V.2 R6.1 | length 112.2
  Top Layer w30: R6.1@2471.2,107.84 3.3V.2@2471.2,220
NetLED3_2: 
NetLED4_1: LED4.1 R23.1 | length 130
  Top Layer w20: R23.1@1303.56,5401 LED4.1@1433.6,5401
NetLED5_2: 2.5V.2 R11.1 | length 113.8
  Top Layer w30: 2.5V.2@2751.2,220 2751.2,108.84 R11.1@2753.04,107
NetLED6_1: LED6.1 R12.1
  other v1: 4476,2972
NetLED7_1: LED7.1 R13.1
  other v1: 4477,2855
NetLED8_1: LED8.1 R14.1
  other v1: 4476,2737
NetLED9_1: LED9.1 R15.1
  other v1: 4472,2619
NetLED10_1: LED10.1 R16.1
  other v1: 4472,2502
NetLED11_1: LED11.1 R17.1
  other v1: 4491,2344
NSTATUS: R18.2 U19.17 | length 103
  Top Layer w10: U19.17@3113.39,1624.25 3157.25,1624.25 3194.44,1661.44 R18.2@3194.44,1668
R1I-232: MAX3232_D.13 P1.4 | length 691.7
  Top Layer w20: v2(717,1895) 789,1967 MAX3232_D.13@845,1967
  Bottom Layer w20: P1.4@232,1777 282,1827 649,1827 v2(717,1895)
R1O-232: MAX3232_D.12 U19.174 | length 1144.4
  Top Layer w8: MAX3232_D.12@845,1917 1093,1917 1582.6,1427.4 U19.174@1786.61,1427.4
R2I-232: MAX3232_D.8 P1.3 | length 272.1
  Top Layer w20: P1.3@332,1777 342,1767 MAX3232_D.8@600,1767
R2O-232: MAX3232_D.9 U19.177 | length 1106.7
  Top Layer w8: MAX3232_D.9@845,1767 1134,1767 1532.65,1368.35 U19.177@1786.61,1368.35
R-GD: J2.56 U5.14 | length 1067.5
  Bottom Layer w8: J2.56@2493.8,4519.7 2493.8,4490.2 2538,4446 2538,4322 2918,3942 U5.14@2918,3627.94
R-GD-S: U5.6 U16.12 | length 215.9
  Bottom Layer w8: U5.6@2968,3346.06 2968,3284 3016,3236 U16.12@3016,3150.02
R-GD-SA: U16.5 U19.64 | length 241
  Top Layer w8: U19.64@2971.65,2553.39 2971.65,2598.65 3016,2643 v1(3016,2711)
  Bottom Layer w8: v1(3016,2711) U16.5@3016,2776
RDA: J2.16 U5.12 | length 1458.8
  Bottom Layer w8: J2.16@2452.25,4878.69 2384,4810.44 2384,4649 2449,4584 2449,4340 2818,3971 U5.12@2818,3627.94
RDA-S: U5.8 U16.11 | length 236.6
  Bottom Layer w8: U5.8@2868,3346.06 2868,3298 2966,3200 U16.11@2966,3150.02
RDA-SA: U16.6 U19.65 | length 228.4
  Top Layer w8: U19.65@2951.97,2553.39 2951.97,2604 2966,2618.03 v1(2966,2711)
  Bottom Layer w8: v1(2966,2711) U16.6@2966,2776
RDN: U19.207 U20.31 | length 1735.1
  Top Layer w8: U20.31@1087.5,466.64 1087.5,591.62 1114.13,618.25 1698.25,618.25 1890,810 2055.87,810 2381.1,1135.23 U19.207@2381.1,1226.61
RESET: C81.2 CP8.1 D1.1 R19.1 RESET1.2 U19.224 | length 2583.4
  Top Layer w8: RESET1.2@1702,77 1702,178 2469,945 2595,945 2715.75,1065.75 U19.224@2715.75,1226.61
  Top Layer w30: CP8.1@1539,39.15 1576.85,77 RESET1.2@1702,77 RESET1.2@1977,77 ; R19.1@2002,228.44 1977,203.44 RESET1.2@1977,77 ; C81.2@2102,16.56 2041.56,77 RESET1.2@1977,77
  Bottom Layer w30: RESET1.2@1977,77 2009.22,109.22 D1.1@2009.22,238.19
RST: U19.197 U20.8 | length 1054.8
  Top Layer w8: U20.8@1441.83,750.1 1441.83,892.83 1483.13,934.13 1945.33,934.13 2184.25,1173.05 U19.197@2184.25,1226.61
RXDA: U20.7 U23.2 | length 777.3
  Top Layer w8: U20.7@1461.51,750.1 v1(1461.51,806.49)
  Bottom Layer w8: U23.2@800,950 1318,950 v1(1461.51,806.49)
RXDB: U20.22 U24.2 | length 493.1
  Top Layer w8: U24.2@800,510 973,683 1146,683 1166.24,703.24 U20.22@1166.24,750.1
SCLK: OSC2.3 U20.55 | length 954
  Top Layer w8: OSC2.3@854,166 1471,166 ; 1472,166 v1(1560,254) ; v1(1560,402) U20.55@1560,466.57
  Bottom Layer w8: v1(1560,254) v1(1560,402)
SP1: J2.46 J2.47 U5.16 | length 821
  Bottom Layer w8: J2.47@2849.81,4227.19 2860.19,4227.19 2933.18,4300.18 3018,4215.35 U5.16@3018,3627.94
SP1-S: U5.4 U16.13 | length 196.9
  Bottom Layer w8: U16.13@3066,3150.02 3068,3152.02 U5.4@3068,3346.06
SP1-SA: U16.4 U19.63 | length 253.5
  Top Layer w8: U19.63@2991.34,2553.39 2991.34,2595.34 3066,2670 v1(3066,2712)
  Bottom Layer w8: v1(3066,2712) U16.4@3066,2776
SP2: J3.27 U19.106 | length 3083.3
  Top Layer w8: J3.27@340,4512.09 466.64,4512.09 1095.17,3883.57 1095.17,3280.33 1275.75,3099.74 1792.75,3099.74 2144.88,2747.61 U19.106@2144.88,2553.39
T: J2.57 U3.3 | length 1393.4
  Top Layer w8: U3.3@1550,4421 1632,4421 1657,4446 1657,4609 1845,4797 2073,4797 2118,4752 2164,4752 2204,4712 2247,4712 2293,4666 2330,4666 2375,4621 2420,4621 2450,4591 2450,4499.44 J2.57@2403.85,4453.3
T1I-232: MAX3232_D.11 U19.175 | length 1131.9
  Top Layer w8: MAX3232_D.11@845,1867 1107,1867 1566.28,1407.72 U19.175@1786.61,1407.72
T1O-232: MAX3232_D.14 P1.6 | length 671
  Top Layer w20: v2(717,2017) MAX3232_D.14@845,2017
  Bottom Layer w20: P1.6@232,1877 372,2017 v2(717,2017)
T2I-232: MAX3232_D.10 U19.176 | length 1119.3
  Top Layer w8: MAX3232_D.10@845,1817 1121,1817 1549.97,1388.03 U19.176@1786.61,1388.03
T2O-232: MAX3232_D.7 P1.5 | length 292.9
  Top Layer w20: P1.5@332,1877 392,1817 MAX3232_D.7@600,1817
T-A: U3.14 U19.88 | length 2342.2
  Top Layer w8: U3.14@1924.02,4421 1836,4421 1701,4286 1701,3477 2499.21,2678.79 U19.88@2499.21,2553.39
TA0: J3.66 U19.139 | length 2711.5
  Top Layer w8: v1(653.5,3665.5) 745.94,3573.06 745.94,2979.61 1609.17,2116.38 U19.139@1786.61,2116.38
  Bottom Layer w8: J3.66@140,3847.91 148.91,3839 266,3839 312,3793 526,3793 v1(653.5,3665.5)
TA1: J3.65 U19.137 | length 2821
  Top Layer w8: v1(631,3721) 761.81,3590.19 761.81,2986.19 1592.25,2155.75 U19.137@1786.61,2155.75
  Bottom Layer w8: J3.65@40,3895.35 162.65,3895.35 204,3854 272,3854 319,3807 545,3807 v1(631,3721)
